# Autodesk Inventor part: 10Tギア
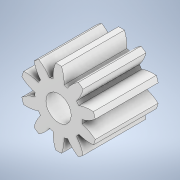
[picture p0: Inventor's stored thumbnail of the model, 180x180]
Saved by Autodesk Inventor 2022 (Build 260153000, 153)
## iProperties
CustomPartVersion: 1
Created: 2024-10
Part Number: 10Tギア
Material: アセタール樹脂、白
Document SubType Name: Modeling
Designer: shimizu
Categories: <?xml version="1.0" encoding="UTF-16"?> <MemberInstance><Categories><FamilyTemplate><FamilyTemplateParameter ValueType="xs:double" Id="1" ObjectReferenceKey="da
Density: 1.425 g/cm^3
Appearance: 滑らか - 白
Author: shimizu
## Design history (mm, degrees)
sketch "Sketch1"
  geometry: C1 r 3 at (0, 0)
  constraints: 1 centre point
  dimensions: "d0" = 6 diameter of C1 (= da_da)
extrude "Extrusion1" new body sketch "Sketch1" distance "d1" = 5 (= da_b); taper "d2" = 0 deg
workplane "Work Plane2"
sketch "Sketch2"
  geometry: C1 r 3 at (0, 0) reference; C2 r 2.5 at (0, 0)
  constraints: 1 centre point, 1 coincident
  dimensions: "d3" = 5 diameter of C2 (= da_d)
feature "ピッチ円直径" sketch "Sketch2" dims "d4" = 10, "d5" = 0
workplane "Work Plane8"
workplane "Work Plane9"
feature "平歯車" dims "da_b" = 5, "da_d" = 5, "da_aw" = 11.75, "da_da" = 6, "da_df" = 3.75, "da_dw" = 5, angle "da_beta" = 0 deg, "da_lefttooth" = 0, "da_righttooth" = 0
sketch "スケッチ3"
  geometry: C1 r 1 at (0, 0); 1 further point
  constraints: 1 centre point, 1 coincident
  dimensions: "d49" = 2 diameter of C1
extrude "押し出し2" cut sketch "スケッチ3" extent not by distance; stored distance "d50" = 0; taper "d51" = 0 deg
body "Solid1"
body "Srf1"
other parameters: "d16" = 11.75 (= da_aw), "d17" = 0, "d34" = 18 deg (computed from da_z), "d39" = 0, "d41" = 0, "d43" = 11.75 (= da_aw), "d46" = 11.75 (= da_aw), "d47" = 0, "d48" = 0
